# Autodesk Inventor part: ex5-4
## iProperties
Author: Administrator
Created: 2001-09
Part Number: ex5-4
Document SubType Name: Modeling
Designer: Administrator
Control State: 0
Master: False
Checked Out: False
PropertySet Name: Design Tracking Control
Length Units: 11272
Angle Units: 11279
Time Units: 11290
Mass Units: 11286
Shininess: 3
Angle Display Precision: 2
Document Length Units: 11272
Document Angle Units: 11286
Document Time Units: 11279
Document Mass Units: 11290
Document Length Units Precision: 3
Document Angle Units Precision: 2
Compacted: False
PropertySet Name: _Private Model Information
Density: 0.0
Volumn: 0.0
Area: 0.0
PropertySet Name: Model Information
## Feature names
1. Revolution1
2. Hole1
3. Shell1
